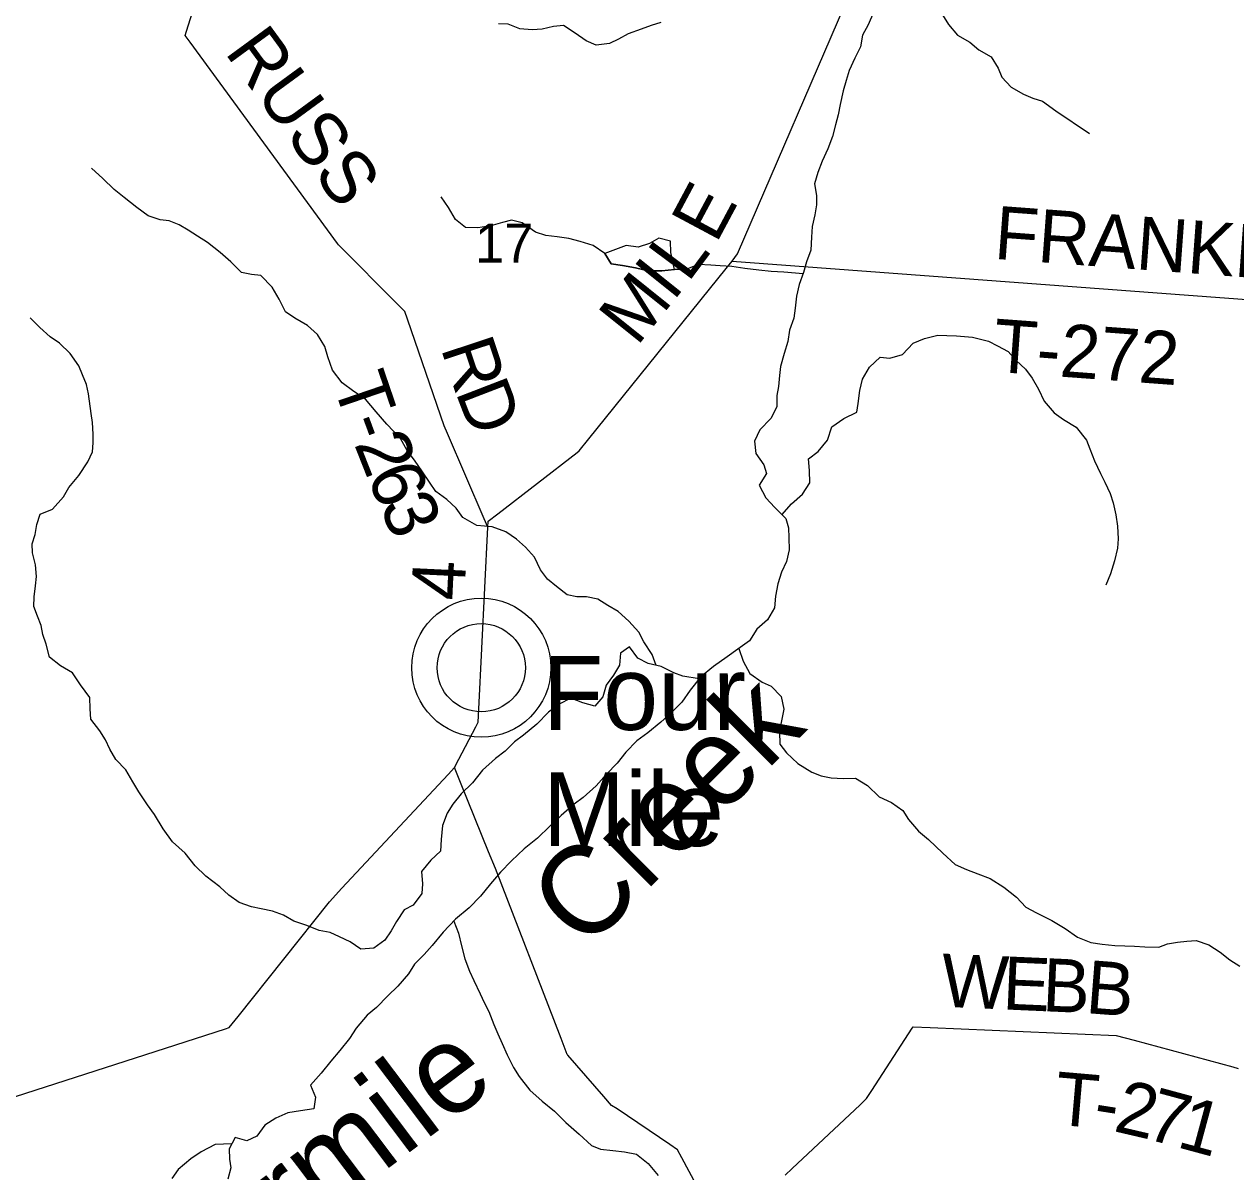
# Model space of a CAD drawing. Extents: x 0 to 34, y 0 to 22.
# Drawn here: x 5.831 to 7.127, y 16.276 to 17.503 of the extents above; entities that cross this region are included whole.
import ezdxf

# ---------------------------------------------------------------- set-up
doc = ezdxf.new("R2010")
doc.units = 0
for name, color, linetype in [('GM_X_County_Road', 7, 'Continuous'), ('GM_X_County_Road_Text', 7, 'Continuous'), ('GM_X_Minor_Lake', 7, 'Continuous'), ('GM_X_Minor_River', 7, 'Continuous'), ('GM_X_Minor_River_Text', 7, 'Continuous'), ('GM_X_Section_Text', 7, 'Continuous'), ('GM_X_Township_Road', 7, 'Continuous'), ('GM_X_Township_Road_Text', 7, 'Continuous'), ('GM_X_Unincorporated', 7, 'Continuous'), ('GM_X_Unincorporated_Location', 7, 'Continuous'), ('GM_X_Unincorporated_Text', 7, 'Continuous')]:
    doc.layers.add(name, color=color, linetype=linetype)

msp = doc.modelspace()

# ---------------------------------------------------------------- linework, layer by layer
at = {"layer": 'GM_X_County_Road'}
for points in [[(6.2915, 16.7083), (6.2962, 16.7172), (6.3143, 16.7518), (6.317, 16.7569), (6.3176, 16.7706), (6.3272, 16.9653), (6.3276, 16.9719), (6.3378, 16.9797), (6.4227, 17.0452), (6.4251, 17.0471), (6.4354, 17.0599), (6.5822, 17.242), (6.5886, 17.2499), (6.5942, 17.2578), (6.8375, 17.8217)], [(5.3691, 16.2545), (5.3828, 16.2597), (5.4119, 16.2704), (5.4359, 16.279), (5.4923, 16.3023), (5.5127, 16.3023), (5.6694, 16.2963), (5.6728, 16.2962), (5.686, 16.3055), (5.702, 16.3168), (5.7051, 16.3189), (5.7202, 16.3238), (5.7575, 16.3358), (6.0466, 16.4289), (6.0506, 16.4302), (6.0602, 16.4422), (6.1578, 16.5648), (6.1712, 16.5792), (6.2848, 16.701), (6.2915, 16.7083)], [(6.5716, 16.2223), (6.5347, 16.291), (6.5302, 16.2995), (6.522, 16.305), (6.4654, 16.3431), (6.4596, 16.347), (6.4514, 16.3564), (6.4129, 16.4005), (6.4122, 16.4013), (6.4056, 16.4184), (6.3353, 16.6002), (6.3279, 16.6183), (6.2987, 16.6905), (6.2915, 16.7083)]]:
    msp.add_lwpolyline(points, dxfattribs=at)
at = {"layer": 'GM_X_Minor_Lake'}
for points in [[(6.5269, 17.2412), (6.5228, 17.2594), (6.5225, 17.2715), (6.51, 17.2746), (6.5002, 17.2689), (6.488, 17.2648), (6.4752, 17.2668), (6.4525, 17.2581)], [(6.4525, 17.2581), (6.4592, 17.2471), (6.4713, 17.2452), (6.4853, 17.2428), (6.4989, 17.2397), (6.5133, 17.2397), (6.5269, 17.2412)]]:
    msp.add_lwpolyline(points, dxfattribs=at)
at = {"layer": 'GM_X_Minor_River'}
for points in [[(6.7398, 17.5159), (6.7341, 17.5027), (6.728, 17.4917), (6.7257, 17.4792), (6.7199, 17.4671), (6.7138, 17.4539), (6.7104, 17.4433), (6.7073, 17.4323), (6.7042, 17.4175), (6.7019, 17.4065), (6.6992, 17.3959), (6.6958, 17.3834), (6.6908, 17.3702), (6.6847, 17.3569), (6.6801, 17.3448), (6.6767, 17.3327), (6.6789, 17.3202), (6.6789, 17.3103), (6.677, 17.2997), (6.6743, 17.2872), (6.6735, 17.2758), (6.6726, 17.2618), (6.6681, 17.2493), (6.665, 17.238), (6.6604, 17.2251), (6.6573, 17.2126), (6.6558, 17.1997), (6.6546, 17.1891), (6.65, 17.1762), (6.6481, 17.1641), (6.6442, 17.1512), (6.6404, 17.1372), (6.6392, 17.1278), (6.6381, 17.116), (6.6365, 17.1062), (6.6365, 17.094), (6.63, 17.0816), (6.6182, 17.0695), (6.6125, 17.0574), (6.614, 17.0441), (6.6226, 17.0323), (6.6252, 17.0228), (6.6176, 17.0103), (6.6244, 16.997), (6.6342, 16.9864), (6.6459, 16.9746), (6.6489, 16.9647), (6.6492, 16.9541), (6.6495, 16.9412), (6.6468, 16.9287), (6.6415, 16.9174), (6.6373, 16.9049), (6.635, 16.8916), (6.6338, 16.8791), (6.6265, 16.8663), (6.6148, 16.8564), (6.6072, 16.844), (6.5947, 16.8349), (6.5833, 16.8266)], [(6.8117, 17.5164), (6.8199, 17.5031), (6.8294, 17.4917), (6.8426, 17.4841), (6.8524, 17.4761), (6.8656, 17.4684), (6.8731, 17.4563), (6.8769, 17.4468), (6.887, 17.4361), (6.9002, 17.4285), (6.9101, 17.4243), (6.9206, 17.4212), (6.9346, 17.4109), (6.9708, 17.3865)], [(6.5124, 17.5054), (6.5018, 17.5021), (6.4912, 17.4983), (6.4772, 17.4931), (6.4669, 17.4874), (6.4575, 17.4829), (6.4431, 17.4811), (6.4325, 17.4856), (6.4208, 17.494), (6.4083, 17.502), (6.3974, 17.5009), (6.3853, 17.4983), (6.3747, 17.4976), (6.3614, 17.4984), (6.349, 17.5034), (6.3387, 17.5038)], [(6.5072, 16.8176), (6.5031, 16.8292), (6.4941, 16.8429), (6.4888, 16.8531), (6.4782, 16.8649), (6.4666, 16.8752), (6.4556, 16.8817), (6.445, 16.8886), (6.4329, 16.8909), (6.4224, 16.8909), (6.4121, 16.8929), (6.4008, 16.902), (6.391, 16.91), (6.3835, 16.9199), (6.3771, 16.9332), (6.3677, 16.9442), (6.3579, 16.9526), (6.3466, 16.9606), (6.3318, 16.9659), (6.3156, 16.9671), (6.3005, 16.9759), (6.2933, 16.9858), (6.2835, 16.9949), (6.2718, 17.0037), (6.2647, 17.0136), (6.2572, 17.0246), (6.2489, 17.0371), (6.241, 17.0474), (6.2338, 17.0603), (6.2191, 17.0755), (6.2078, 17.0889), (6.1965, 17.1025), (6.1841, 17.1106), (6.1716, 17.1197), (6.1611, 17.1334), (6.1562, 17.1478), (6.1529, 17.1588), (6.145, 17.1714), (6.1344, 17.1813), (6.1208, 17.1889), (6.111, 17.1957), (6.1042, 17.2094), (6.0967, 17.2223), (6.0843, 17.2345), (6.0745, 17.2357), (6.0639, 17.238), (6.0522, 17.2494), (6.0409, 17.2593), (6.0273, 17.27), (6.0167, 17.2769), (6.0069, 17.283), (5.9971, 17.2887), (5.9865, 17.2933), (5.9767, 17.2941), (5.9638, 17.2983), (5.9518, 17.3074), (5.9382, 17.3181), (5.9276, 17.3265), (5.9156, 17.3383), (5.9035, 17.3493)], [(6.6645, 17.2366), (6.6438, 17.2381), (6.6302, 17.2389), (6.617, 17.2404), (6.6022, 17.242), (6.5882, 17.2443), (6.5757, 17.2451), (6.5659, 17.2456), (6.5527, 17.2464), (6.539, 17.2411), (6.5269, 17.2412), (6.5133, 17.2397), (6.4989, 17.2397), (6.4853, 17.2428), (6.4713, 17.2452), (6.4592, 17.2471), (6.4525, 17.2581), (6.44, 17.2669), (6.426, 17.2711), (6.4139, 17.2742), (6.4015, 17.2761), (6.3894, 17.2773), (6.3784, 17.2811), (6.3641, 17.2911), (6.3527, 17.2938), (6.3429, 17.2915), (6.3304, 17.2878), (6.3164, 17.2856), (6.3035, 17.286), (6.2926, 17.2944), (6.2851, 17.3073), (6.2772, 17.3187)], [(5.8981, 17.1181), (5.8936, 17.1283), (5.8899, 17.1382), (5.8805, 17.1511), (5.8691, 17.1622), (5.8593, 17.169), (5.848, 17.1789), (5.8378, 17.1892)], [(6.6417, 16.9788), (6.652, 16.9905), (6.6637, 17.0007), (6.6717, 17.0128), (6.6714, 17.026), (6.6703, 17.0386), (6.6806, 17.0465), (6.6904, 17.0586), (6.695, 17.0726), (6.7079, 17.0816), (6.7219, 17.0884), (6.7235, 17.0979), (6.7251, 17.1115), (6.7281, 17.1236), (6.7354, 17.1365), (6.7468, 17.1474), (6.7573, 17.1463), (6.7706, 17.15), (6.782, 17.1621), (6.7941, 17.1673), (6.8085, 17.1707), (6.8183, 17.1703), (6.8286, 17.1702), (6.8456, 17.1687), (6.8626, 17.1644), (6.8724, 17.1595), (6.8837, 17.1534), (6.8924, 17.1438), (6.9022, 17.1343), (6.9093, 17.1248), (6.9161, 17.1131), (6.9221, 17.1001), (6.933, 17.0876), (6.9428, 17.0807), (6.9564, 17.0723), (6.9674, 17.0586), (6.9711, 17.0492), (6.976, 17.0363), (6.9824, 17.023), (6.9872, 17.0135), (6.9929, 17.0013), (6.9962, 16.9914), (6.9988, 16.9785), (7.0007, 16.9664), (7.0014, 16.9528), (7.0006, 16.9429), (6.9975, 16.9293), (6.9933, 16.9156), (6.9883, 16.9035)], [(6.5533, 16.8032), (6.5359, 16.8059), (6.5261, 16.8098), (6.5125, 16.8163), (6.4989, 16.8197), (6.4876, 16.8255), (6.4789, 16.8376), (6.469, 16.8308), (6.4682, 16.818), (6.4618, 16.807), (6.4538, 16.7964), (6.4503, 16.7839), (6.4416, 16.7741), (6.4287, 16.7775), (6.4159, 16.7825), (6.4034, 16.7761), (6.392, 16.7675), (6.3795, 16.7546), (6.3654, 16.7429), (6.3556, 16.7358), (6.3457, 16.7259), (6.3355, 16.718), (6.3214, 16.7056), (6.3108, 16.692), (6.2986, 16.6803), (6.2899, 16.6693), (6.2838, 16.6595), (6.2788, 16.6462), (6.2773, 16.6314), (6.2765, 16.6189), (6.2662, 16.6091), (6.2563, 16.597), (6.2574, 16.5841), (6.2566, 16.5735), (6.2475, 16.561), (6.2376, 16.5561), (6.2297, 16.5437), (6.2239, 16.5335), (6.2171, 16.5236), (6.2053, 16.5153), (6.1913, 16.5139), (6.18, 16.5219), (6.1687, 16.5272), (6.1585, 16.5318), (6.1468, 16.5341), (6.1335, 16.5395), (6.1199, 16.5441), (6.1086, 16.5506), (6.0969, 16.5548), (6.0848, 16.5571), (6.0746, 16.5594), (6.0614, 16.564), (6.0504, 16.5717), (6.0406, 16.5808), (6.0255, 16.5922), (6.0142, 16.6033), (6.0037, 16.6169), (5.9901, 16.6287), (5.98, 16.6428), (5.9706, 16.658), (5.9634, 16.6683), (5.954, 16.6823), (5.9476, 16.693), (5.9401, 16.7059), (5.9295, 16.7169), (5.9228, 16.7279), (5.9183, 16.7378), (5.9123, 16.7477), (5.9025, 16.7599), (5.9021, 16.7712), (5.9014, 16.7834), (5.8916, 16.7967), (5.883, 16.8096), (5.8701, 16.8172), (5.8584, 16.8264), (5.8547, 16.8404), (5.8513, 16.8507), (5.8495, 16.8601), (5.8457, 16.8704), (5.8416, 16.8806), (5.842, 16.8909), (5.8436, 16.9026), (5.8444, 16.9128), (5.8433, 16.925), (5.8403, 16.9379), (5.84, 16.9477), (5.843, 16.9576), (5.845, 16.9682), (5.8484, 16.9795), (5.8617, 16.9848), (5.8735, 16.998), (5.8792, 17.0079), (5.8898, 17.0207), (5.8993, 17.0355), (5.9043, 17.0461), (5.9051, 17.0555), (5.9051, 17.065), (5.9044, 17.0775), (5.9029, 17.087), (5.9, 17.1082), (5.8981, 17.1181)], [(6.5957, 16.8356), (6.6003, 16.822), (6.6074, 16.8091), (6.6206, 16.7996), (6.6304, 16.7954), (6.641, 16.7843), (6.644, 16.7707), (6.6409, 16.7566), (6.6393, 16.7464), (6.6397, 16.7335), (6.6465, 16.724), (6.6589, 16.7126), (6.6736, 16.7034), (6.6838, 16.6996), (6.6944, 16.6973), (6.7073, 16.6965), (6.7205, 16.6968), (6.7333, 16.6892), (6.7458, 16.677), (6.759, 16.6709), (6.7711, 16.6625), (6.7771, 16.6526), (6.788, 16.6401), (6.7986, 16.6313), (6.814, 16.6169), (6.8272, 16.6047), (6.8393, 16.5993), (6.8514, 16.5947), (6.8646, 16.5898), (6.879, 16.5802), (6.8925, 16.5696), (6.9027, 16.5589), (6.914, 16.5528), (6.9303, 16.5448), (6.9446, 16.536), (6.9578, 16.5268), (6.9722, 16.5211), (6.9843, 16.5195), (6.9979, 16.518), (7.0085, 16.5176), (7.0187, 16.5171), (7.03, 16.5167), (7.0448, 16.5163), (7.0543, 16.5197), (7.0649, 16.5215), (7.0747, 16.5226), (7.0849, 16.5233), (7.0985, 16.5187), (7.1106, 16.5107), (7.1208, 16.5027), (7.1314, 16.4959)], [(6.5833, 16.8266), (6.5685, 16.8164), (6.5548, 16.8051), (6.5438, 16.7911), (6.5347, 16.7783), (6.5225, 16.7662), (6.5123, 16.7568), (6.4982, 16.7454), (6.4865, 16.7368), (6.4747, 16.7247), (6.4656, 16.713), (6.4542, 16.7013), (6.4432, 16.6888), (6.4291, 16.6763), (6.4196, 16.6692), (6.4056, 16.6571), (6.3935, 16.6458), (6.3805, 16.6329), (6.3661, 16.6212), (6.3525, 16.6084), (6.3407, 16.5963), (6.3301, 16.5838), (6.3194, 16.5706), (6.3073, 16.5582), (6.2928, 16.5461), (6.2795, 16.5321), (6.2678, 16.5181), (6.259, 16.5083), (6.2488, 16.4981), (6.2423, 16.4875), (6.2309, 16.4743), (6.2203, 16.4641), (6.2081, 16.4516), (6.1983, 16.4433), (6.1865, 16.4294), (6.1793, 16.4184), (6.169, 16.4055), (6.1595, 16.3942), (6.1489, 16.3814), (6.1375, 16.3685), (6.1431, 16.3556), (6.1411, 16.3431), (6.1268, 16.3413), (6.1135, 16.339), (6.1006, 16.3334), (6.0889, 16.3259), (6.0801, 16.3141), (6.0695, 16.3089), (6.057, 16.3127), (6.0506, 16.3006), (6.0509, 16.2896), (6.0524, 16.2801), (6.0493, 16.268)], [(6.2909, 16.5441), (6.2958, 16.5313), (6.2992, 16.5176), (6.3025, 16.5036), (6.3078, 16.4907), (6.3123, 16.4804), (6.319, 16.4664), (6.3235, 16.4569), (6.3284, 16.4474), (6.3337, 16.4333), (6.3378, 16.4235), (6.3427, 16.4132), (6.3479, 16.4011), (6.3547, 16.3874), (6.3607, 16.3779), (6.372, 16.3634), (6.3852, 16.3516), (6.3984, 16.3406), (6.4108, 16.3288), (6.4248, 16.3162), (6.438, 16.3041), (6.4478, 16.3002), (6.461, 16.2987), (6.4735, 16.2971), (6.4864, 16.2948), (6.4988, 16.2849), (6.5093, 16.2719)], [(6.0534, 16.3059), (6.0358, 16.3052), (6.0207, 16.2973), (6.0097, 16.2898), (5.996, 16.2785), (5.9892, 16.2686)]]:
    msp.add_lwpolyline(points, dxfattribs=at)
at = {"layer": 'GM_X_Township_Road'}
for points in [[(6.3272, 16.9653), (6.3233, 16.9744), (6.2841, 17.0658), (6.2805, 17.074), (6.277, 17.0843), (6.2413, 17.1878), (6.2384, 17.196), (6.2306, 17.2039), (6.1677, 17.2676), (6.1664, 17.2689), (6.1557, 17.2835), (6.009, 17.4841), (6.0036, 17.4915), (6.0069, 17.5018), (6.0249, 17.5587)], [(6.5886, 17.2499), (7.8282, 17.1576), (7.9156, 17.2654)], [(6.6451, 16.2722), (6.6528, 16.2795), (6.7253, 16.3476), (6.7323, 16.3542), (6.7379, 16.3628), (6.7812, 16.4297), (6.782, 16.4309), (6.8004, 16.4302), (6.9993, 16.4218), (7.0185, 16.4167), (7.1241, 16.3881), (7.1299, 16.3865)]]:
    msp.add_lwpolyline(points, dxfattribs=at)
at = {"layer": 'GM_X_Unincorporated'}
for radius in [0.0744, 0.0472]:
    msp.add_circle((6.3202, 16.8151), radius, dxfattribs=at)
at = {"layer": 'GM_X_Unincorporated_Location'}
msp.add_line((6.3202, 16.8151), (6.3202, 16.8151), dxfattribs=at)

# ---------------------------------------------------------------- texts
at = {"layer": 'GM_X_County_Road_Text'}
for s, rotation, p in [('E', 61.8704, (6.5714, 17.2678)), ('L', 53.3902, (6.5413, 17.2261)), ('I', 51.3222, (6.5253, 17.2061)), ('M', 51.2885, (6.4867, 17.158)), ('4', 87.2752, (6.302, 16.8863))]:
    msp.add_text(s, height=0.0568, rotation=rotation, dxfattribs=at).set_placement(p)
at = {"layer": 'GM_X_Minor_River_Text'}
for s, rotation, p in [('Creek', 45.0029, (6.4312, 16.5104)), ('Fourmile', 37.0021, (5.9447, 16.0715))]:
    msp.add_text(s, height=0.0947, rotation=rotation, dxfattribs=at).set_placement(p)
at = {"layer": 'GM_X_Section_Text'}
msp.add_text('17', height=0.04186, rotation=0, dxfattribs=at).set_placement((6.3136, 17.2484))
at = {"layer": 'GM_X_Township_Road_Text'}
for s, height, rotation, p in [('RUSS', 0.05682, 306.2098, (6.045, 17.4735)), ('FRANKLIN', 0.05682, 355.7789, (6.8678, 17.2526)), ('T-272', 0.05682, 355.7742, (6.8664, 17.1319)), ('R', 0.0568, 288.393, (6.2766, 17.1572)), ('T', 0.0568, 288.889, (6.161, 17.1195)), ('D', 0.0568, 291.0828, (6.2922, 17.1103)), ('-', 0.0568, 290.2911, (6.1753, 17.0779)), ('2', 0.0568, 291.5403, (6.1839, 17.0547)), ('6', 0.0568, 292.7366, (6.1972, 17.021)), ('3', 0.0568, 293.1368, (6.2109, 16.9883)), ('W', 0.0568, 357.4787, (6.8113, 16.4526)), ('E', 0.0568, 357.4749, (6.877, 16.4497)), ('B', 0.0568, 357.4426, (6.9195, 16.4478)), ('B', 0.0568, 355.5501, (6.9656, 16.4458)), ('T', 0.0568, 355.0651, (6.932, 16.3266)), ('2', 0.0568, 346.9138, (6.9952, 16.3197)), ('7', 0.0568, 344.8759, (7.0288, 16.3119)), ('-', 0.0568, 350.9894, (6.9732, 16.3231)), ('1', 0.0568, 344.8759, (7.0626, 16.3027))]:
    msp.add_text(s, height=height, rotation=rotation, dxfattribs=at).set_placement(p)
at = {"layer": 'GM_X_Unincorporated_Text'}
for s, p in [('Four', (6.3861, 16.7486)), ('Mile', (6.3861, 16.6244))]:
    msp.add_text(s, height=0.07898, rotation=0, dxfattribs=at).set_placement(p)

doc.saveas('drawing.dxf')
